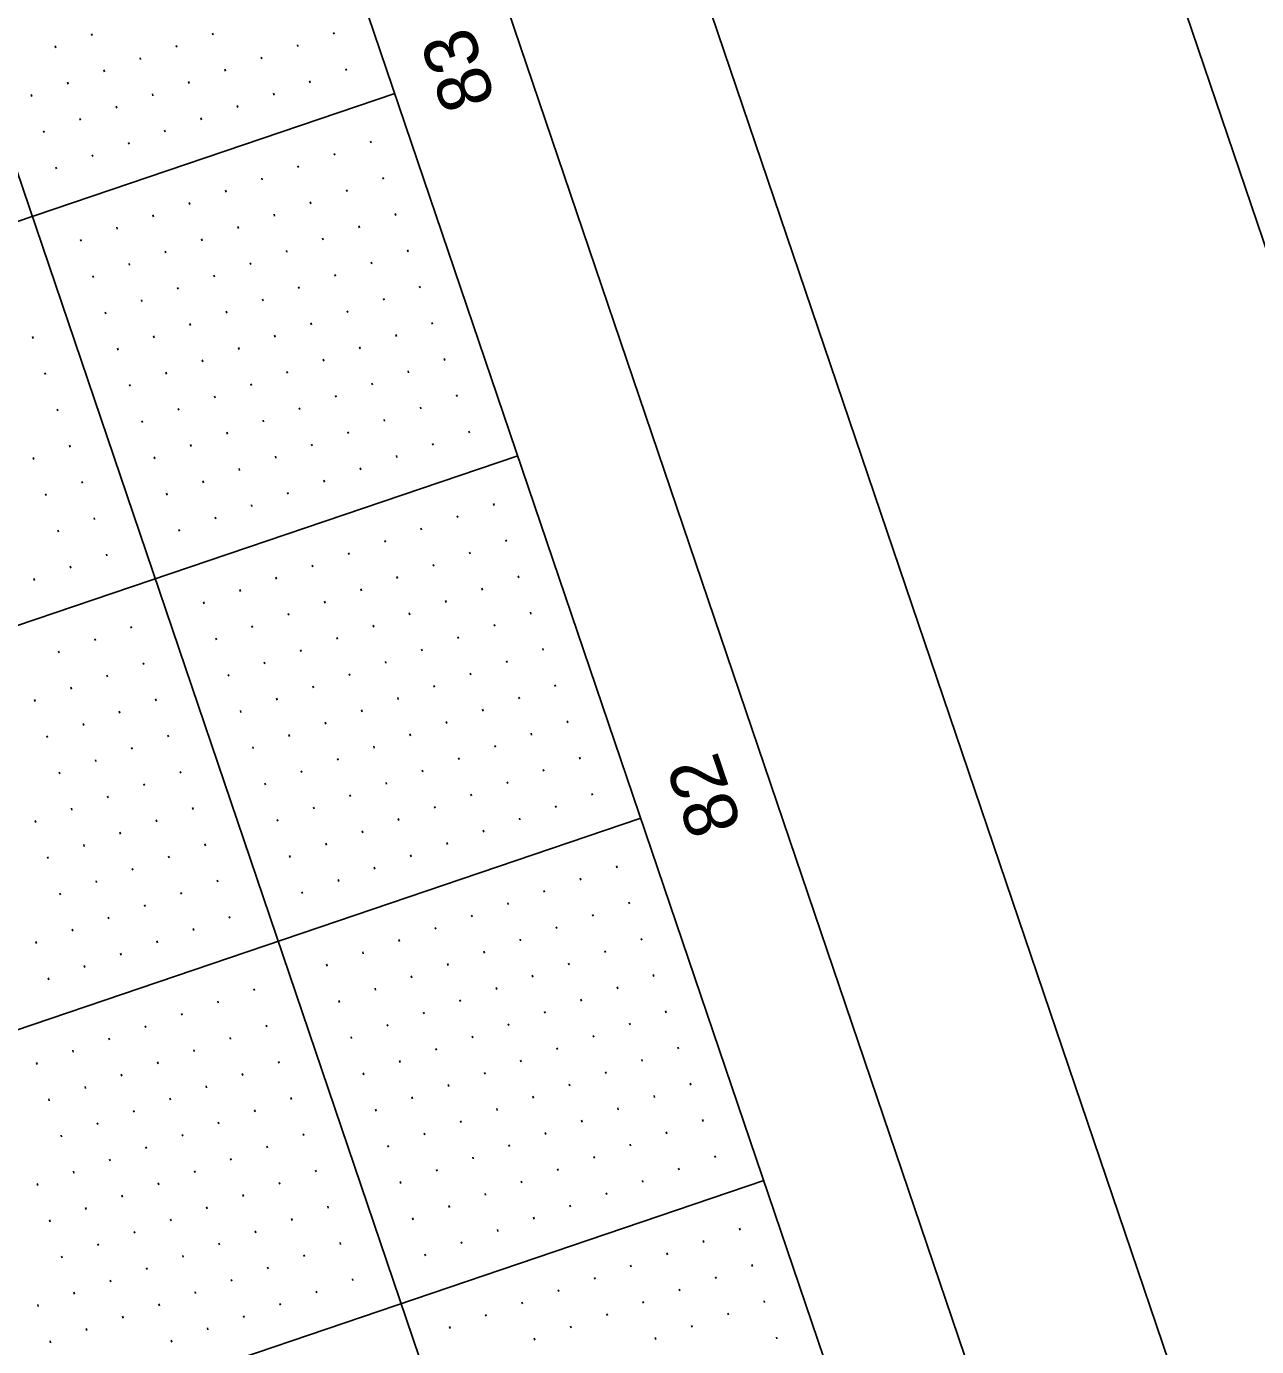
# Model space of a CAD drawing. Extents: x 2150800 to 2152547, y 141860 to 143950.
# Drawn here: x 2151980.1 to 2152140.8, y 143201.8 to 143374.3 of the extents above; entities that cross this region are included whole.
import ezdxf

# ---------------------------------------------------------------- set-up
doc = ezdxf.new("R2010")
doc.units = 0
for name, color, linetype in [('SHT_Plan_Profile_Sheet_Sta_Txt', 7, 'Continuous'), ('SHT_Plot_Shape_Full', 7, 'Continuous'), ('SHT_Plot_Shape_Half', 7, 'Continuous'), ('SHT_Profile_Grid_Major', 7, 'Continuous'), ('SHT_Profile_Grid_Minor', 7, 'Continuous'), ('SHT_Sheet_Border', 7, 'Continuous')]:
    doc.layers.add(name, color=color, linetype=linetype)

msp = doc.modelspace()

# ---------------------------------------------------------------- linework, layer by layer
at = {"layer": 'SHT_Plot_Shape_Full'}
msp.add_lwpolyline([(2151378.63, 141860.13), (2150800.36, 143564.71), (2151936.74, 143950.23), (2152515.02, 142245.65)], close=True, dxfattribs=at)
at = {"layer": 'SHT_Plot_Shape_Half'}
msp.add_lwpolyline([(2151391.39, 141950.92), (2150845.24, 143560.8), (2151886.93, 143914.19), (2152433.08, 142304.31)], close=True, dxfattribs=at)
at = {"layer": 'SHT_Profile_Grid_Major'}
for p, q in [((2152314.16, 142366.92), (2151808.17, 143858.43)), ((2152028.2, 143365.49), (2151554.7, 143204.86)), ((2152044.26, 143318.14), (2151570.77, 143157.51)), ((2152060.32, 143270.79), (2151586.83, 143110.16)), ((2152076.39, 143223.44), (2151602.89, 143062.81))]:
    msp.add_line(p, q, dxfattribs=at)
at = {"layer": 'SHT_Profile_Grid_Minor'}
for p, q in [((2151988.67, 143373.06), (2151988.59, 143373.3)), ((2152004.48, 143373.15), (2152004.4, 143373.39)), ((2152020.29, 143373.23), (2152020.21, 143373.47)), ((2151983.93, 143371.46), (2151983.85, 143371.7)), ((2151999.74, 143371.54), (2151999.66, 143371.78)), ((2152015.56, 143371.63), (2152015.48, 143371.86)), ((2151995.01, 143369.94), (2151994.93, 143370.17)), ((2152010.82, 143370.02), (2152010.74, 143370.26)), ((2151990.27, 143368.33), (2151990.19, 143368.57)), ((2152006.09, 143368.41), (2152006.01, 143368.65)), ((2152021.9, 143368.5), (2152021.82, 143368.73)), ((2151985.54, 143366.72), (2151985.46, 143366.96)), ((2152001.35, 143366.81), (2152001.27, 143367.04)), ((2152017.16, 143366.89), (2152017.08, 143367.13)), ((2151980.8, 143365.12), (2151980.72, 143365.35)), ((2151996.62, 143365.2), (2151996.54, 143365.44)), ((2152007.69, 143363.68), (2152007.61, 143363.92)), ((2152012.43, 143365.29), (2152012.35, 143365.52)), ((2151987.15, 143361.99), (2151987.07, 143362.23)), ((2151991.88, 143363.59), (2151991.8, 143363.83)), ((2152002.96, 143362.07), (2152002.88, 143362.31)), ((2151982.41, 143360.38), (2151982.33, 143360.62)), ((2151998.22, 143360.47), (2151998.14, 143360.7)), ((2151993.49, 143358.86), (2151993.41, 143359.1)), ((2152025.11, 143359.03), (2152025.03, 143359.26)), ((2151988.75, 143357.25), (2151988.67, 143357.49)), ((2152020.37, 143357.42), (2152020.29, 143357.66)), ((2151984.02, 143355.65), (2151983.94, 143355.88)), ((2152015.64, 143355.82), (2152015.56, 143356.05)), ((2152010.9, 143354.21), (2152010.82, 143354.45)), ((2152026.72, 143354.29), (2152026.64, 143354.53)), ((2152006.17, 143352.6), (2152006.09, 143352.84)), ((2152021.98, 143352.69), (2152021.9, 143352.92)), ((2152001.43, 143351), (2152001.35, 143351.23)), ((2152017.25, 143351.08), (2152017.17, 143351.32)), ((2151996.7, 143349.39), (2151996.62, 143349.63)), ((2152012.51, 143349.47), (2152012.43, 143349.71)), ((2152028.32, 143349.56), (2152028.24, 143349.79)), ((2151991.96, 143347.78), (2151991.88, 143348.02)), ((2152007.78, 143347.87), (2152007.7, 143348.1)), ((2152023.59, 143347.95), (2152023.51, 143348.19)), ((2151987.23, 143346.18), (2151987.15, 143346.41)), ((2152003.04, 143346.26), (2152002.96, 143346.5)), ((2152014.12, 143344.74), (2152014.04, 143344.98)), ((2152018.85, 143346.35), (2152018.77, 143346.58)), ((2152029.93, 143344.82), (2152029.85, 143345.06)), ((2151993.57, 143343.05), (2151993.49, 143343.29)), ((2151998.31, 143344.66), (2151998.23, 143344.89)), ((2152009.38, 143343.13), (2152009.3, 143343.37)), ((2152025.19, 143343.22), (2152025.11, 143343.45)), ((2151988.84, 143341.44), (2151988.76, 143341.68)), ((2152004.65, 143341.53), (2152004.57, 143341.76)), ((2152020.46, 143341.61), (2152020.38, 143341.85)), ((2151999.91, 143339.92), (2151999.83, 143340.16)), ((2152015.72, 143340), (2152015.64, 143340.24)), ((2152031.53, 143340.09), (2152031.45, 143340.32)), ((2151995.18, 143338.31), (2151995.1, 143338.55)), ((2152010.99, 143338.4), (2152010.91, 143338.63)), ((2152026.8, 143338.48), (2152026.72, 143338.72)), ((2151990.44, 143336.71), (2151990.36, 143336.94)), ((2152006.25, 143336.79), (2152006.17, 143337.03)), ((2152022.06, 143336.88), (2152021.98, 143337.11)), ((2152001.52, 143335.19), (2152001.44, 143335.42)), ((2152017.33, 143335.27), (2152017.25, 143335.51)), ((2152033.14, 143335.35), (2152033.06, 143335.59)), ((2151980.97, 143333.49), (2151980.89, 143333.73)), ((2151996.78, 143333.58), (2151996.7, 143333.82)), ((2152012.59, 143333.66), (2152012.51, 143333.9)), ((2152028.41, 143333.75), (2152028.33, 143333.98)), ((2151992.05, 143331.97), (2151991.97, 143332.21)), ((2152007.86, 143332.06), (2152007.78, 143332.29)), ((2152023.67, 143332.14), (2152023.59, 143332.38)), ((2152003.13, 143330.45), (2152003.04, 143330.69)), ((2152018.94, 143330.53), (2152018.86, 143330.77)), ((2152034.75, 143330.62), (2152034.67, 143330.85)), ((2151982.58, 143328.76), (2151982.5, 143329)), ((2151998.39, 143328.84), (2151998.31, 143329.08)), ((2152014.2, 143328.93), (2152014.12, 143329.16)), ((2152030.01, 143329.01), (2152029.93, 143329.25)), ((2151993.66, 143327.24), (2151993.57, 143327.47)), ((2152004.73, 143325.72), (2152004.65, 143325.95)), ((2152009.47, 143327.32), (2152009.39, 143327.56)), ((2152020.54, 143325.8), (2152020.46, 143326.04)), ((2152025.28, 143327.41), (2152025.2, 143327.64)), ((2152036.35, 143325.88), (2152036.27, 143326.12)), ((2151984.19, 143324.02), (2151984.1, 143324.26)), ((2152000, 143324.11), (2151999.92, 143324.35)), ((2152015.81, 143324.19), (2152015.73, 143324.43)), ((2152031.62, 143324.28), (2152031.54, 143324.51)), ((2151995.26, 143322.5), (2151995.18, 143322.74)), ((2152011.07, 143322.59), (2152010.99, 143322.82)), ((2152026.88, 143322.67), (2152026.8, 143322.91)), ((2152006.34, 143320.98), (2152006.26, 143321.22)), ((2152022.15, 143321.06), (2152022.07, 143321.3)), ((2152037.96, 143321.15), (2152037.88, 143321.39)), ((2151985.79, 143319.29), (2151985.71, 143319.53)), ((2152001.6, 143319.37), (2152001.52, 143319.61)), ((2152017.41, 143319.46), (2152017.33, 143319.69)), ((2152033.22, 143319.54), (2152033.14, 143319.78)), ((2151981.06, 143317.68), (2151980.98, 143317.92)), ((2151996.87, 143317.77), (2151996.79, 143318)), ((2152012.68, 143317.85), (2152012.6, 143318.09)), ((2152028.49, 143317.94), (2152028.41, 143318.17)), ((2152007.94, 143316.25), (2152007.86, 143316.48)), ((2152023.76, 143316.33), (2152023.67, 143316.57)), ((2151987.4, 143314.56), (2151987.32, 143314.79)), ((2152003.21, 143314.64), (2152003.13, 143314.88)), ((2152019.02, 143314.72), (2152018.94, 143314.96)), ((2151982.66, 143312.95), (2151982.58, 143313.19)), ((2151998.47, 143313.03), (2151998.39, 143313.27)), ((2152014.29, 143313.12), (2152014.2, 143313.35)), ((2152009.55, 143311.51), (2152009.47, 143311.75)), ((2152041.17, 143311.68), (2152041.09, 143311.92)), ((2151989, 143309.82), (2151988.92, 143310.06)), ((2152004.82, 143309.9), (2152004.74, 143310.14)), ((2152031.7, 143308.47), (2152031.62, 143308.7)), ((2152036.44, 143310.07), (2152036.36, 143310.31)), ((2151984.27, 143308.21), (2151984.19, 143308.45)), ((2152000.08, 143308.3), (2152000, 143308.53)), ((2152026.97, 143306.86), (2152026.89, 143307.1)), ((2152042.78, 143306.94), (2152042.7, 143307.18)), ((2151990.61, 143305.09), (2151990.53, 143305.32)), ((2152022.23, 143305.25), (2152022.15, 143305.49)), ((2152038.04, 143305.34), (2152037.96, 143305.57)), ((2151985.88, 143303.48), (2151985.8, 143303.72)), ((2152017.5, 143303.65), (2152017.42, 143303.88)), ((2152033.31, 143303.73), (2152033.23, 143303.97)), ((2151981.14, 143301.87), (2151981.06, 143302.11)), ((2152012.76, 143302.04), (2152012.68, 143302.28)), ((2152028.57, 143302.12), (2152028.49, 143302.36)), ((2152044.39, 143302.21), (2152044.3, 143302.45)), ((2152008.03, 143300.43), (2152007.95, 143300.67)), ((2152023.84, 143300.52), (2152023.76, 143300.75)), ((2152039.65, 143300.6), (2152039.57, 143300.84)), ((2152003.29, 143298.83), (2152003.21, 143299.06)), ((2152019.1, 143298.91), (2152019.02, 143299.15)), ((2152034.92, 143299), (2152034.84, 143299.23)), ((2152014.37, 143297.31), (2152014.29, 143297.54)), ((2152030.18, 143297.39), (2152030.1, 143297.63)), ((2152045.99, 143297.47), (2152045.91, 143297.71)), ((2151993.82, 143295.62), (2151993.74, 143295.85)), ((2152009.63, 143295.7), (2152009.55, 143295.94)), ((2152025.45, 143295.78), (2152025.37, 143296.02)), ((2152041.26, 143295.87), (2152041.18, 143296.1)), ((2151989.09, 143294.01), (2151989.01, 143294.25)), ((2152004.9, 143294.09), (2152004.82, 143294.33)), ((2152020.71, 143294.18), (2152020.63, 143294.41)), ((2152036.52, 143294.26), (2152036.44, 143294.5)), ((2151984.35, 143292.4), (2151984.27, 143292.64)), ((2152015.98, 143292.57), (2152015.9, 143292.81)), ((2152031.79, 143292.65), (2152031.71, 143292.89)), ((2152047.6, 143292.74), (2152047.52, 143292.98)), ((2151995.43, 143290.88), (2151995.35, 143291.12)), ((2152011.24, 143290.96), (2152011.16, 143291.2)), ((2152027.05, 143291.05), (2152026.97, 143291.29)), ((2152038.13, 143289.53), (2152038.05, 143289.76)), ((2152042.86, 143291.13), (2152042.78, 143291.37)), ((2151990.69, 143289.27), (2151990.61, 143289.51)), ((2152006.51, 143289.36), (2152006.43, 143289.59)), ((2152017.58, 143287.84), (2152017.5, 143288.07)), ((2152022.32, 143289.44), (2152022.24, 143289.68)), ((2152033.39, 143287.92), (2152033.31, 143288.16)), ((2152049.2, 143288), (2152049.12, 143288.24)), ((2151981.22, 143286.06), (2151981.14, 143286.3)), ((2151985.96, 143287.67), (2151985.88, 143287.9)), ((2151997.04, 143286.15), (2151996.96, 143286.38)), ((2152012.85, 143286.23), (2152012.77, 143286.47)), ((2152028.66, 143286.31), (2152028.58, 143286.55)), ((2152044.47, 143286.4), (2152044.39, 143286.63)), ((2151992.3, 143284.54), (2151992.22, 143284.78)), ((2152008.11, 143284.62), (2152008.03, 143284.86)), ((2152023.92, 143284.71), (2152023.84, 143284.94)), ((2152039.73, 143284.79), (2152039.65, 143285.03)), ((2151987.57, 143282.93), (2151987.49, 143283.17)), ((2152019.19, 143283.1), (2152019.11, 143283.34)), ((2152035, 143283.18), (2152034.92, 143283.42)), ((2152050.81, 143283.27), (2152050.73, 143283.51)), ((2151982.83, 143281.33), (2151982.75, 143281.56)), ((2151998.64, 143281.41), (2151998.56, 143281.65)), ((2152014.45, 143281.49), (2152014.37, 143281.73)), ((2152030.26, 143281.58), (2152030.18, 143281.82)), ((2152046.08, 143281.66), (2152046, 143281.9)), ((2151993.91, 143279.8), (2151993.83, 143280.04)), ((2152009.72, 143279.89), (2152009.64, 143280.12)), ((2152025.53, 143279.97), (2152025.45, 143280.21)), ((2152041.34, 143280.06), (2152041.26, 143280.29)), ((2151989.17, 143278.2), (2151989.09, 143278.43)), ((2152020.79, 143278.37), (2152020.71, 143278.6)), ((2152036.61, 143278.45), (2152036.53, 143278.69)), ((2152052.42, 143278.53), (2152052.34, 143278.77)), ((2151984.44, 143276.59), (2151984.36, 143276.83)), ((2152000.25, 143276.68), (2152000.17, 143276.91)), ((2152016.06, 143276.76), (2152015.98, 143277)), ((2152031.87, 143276.84), (2152031.79, 143277.08)), ((2152047.68, 143276.93), (2152047.6, 143277.16)), ((2151995.51, 143275.07), (2151995.43, 143275.31)), ((2152011.32, 143275.15), (2152011.24, 143275.39)), ((2152027.14, 143275.24), (2152027.06, 143275.47)), ((2152042.95, 143275.32), (2152042.87, 143275.56)), ((2151990.78, 143273.46), (2151990.7, 143273.7)), ((2152022.4, 143273.63), (2152022.32, 143273.87)), ((2152038.21, 143273.71), (2152038.13, 143273.95)), ((2152054.02, 143273.8), (2152053.94, 143274.04)), ((2151986.04, 143271.86), (2151985.96, 143272.09)), ((2152001.85, 143271.94), (2152001.77, 143272.18)), ((2152017.67, 143272.02), (2152017.59, 143272.26)), ((2152028.74, 143270.5), (2152028.66, 143270.74)), ((2152033.48, 143272.11), (2152033.4, 143272.35)), ((2152044.55, 143270.59), (2152044.47, 143270.82)), ((2152049.29, 143272.19), (2152049.21, 143272.43)), ((2151981.31, 143270.25), (2151981.23, 143270.49)), ((2151997.12, 143270.33), (2151997.04, 143270.57)), ((2152012.93, 143270.42), (2152012.85, 143270.65)), ((2152024.01, 143268.9), (2152023.93, 143269.13)), ((2152039.82, 143268.98), (2152039.74, 143269.22)), ((2151987.65, 143267.12), (2151987.57, 143267.36)), ((2151992.38, 143268.73), (2151992.3, 143268.96)), ((2152003.46, 143267.21), (2152003.38, 143267.44)), ((2152019.27, 143267.29), (2152019.19, 143267.53)), ((2152035.08, 143267.37), (2152035, 143267.61)), ((2151982.91, 143265.52), (2151982.83, 143265.75)), ((2151998.73, 143265.6), (2151998.65, 143265.84)), ((2152014.54, 143265.68), (2152014.46, 143265.92)), ((2152030.35, 143265.77), (2152030.27, 143266)), ((2151993.99, 143263.99), (2151993.91, 143264.23)), ((2152025.61, 143264.16), (2152025.53, 143264.4)), ((2152057.24, 143264.33), (2152057.16, 143264.57)), ((2151989.26, 143262.39), (2151989.18, 143262.62)), ((2152005.07, 143262.47), (2152004.99, 143262.71)), ((2152020.88, 143262.55), (2152020.8, 143262.79)), ((2152052.5, 143262.72), (2152052.42, 143262.96)), ((2151984.52, 143260.78), (2151984.44, 143261.02)), ((2152000.33, 143260.86), (2152000.25, 143261.1)), ((2152016.14, 143260.95), (2152016.06, 143261.19)), ((2152047.77, 143261.12), (2152047.69, 143261.35)), ((2151995.6, 143259.26), (2151995.52, 143259.49)), ((2152043.03, 143259.51), (2152042.95, 143259.75)), ((2152058.84, 143259.59), (2152058.76, 143259.83)), ((2151990.86, 143257.65), (2151990.78, 143257.89)), ((2152006.67, 143257.74), (2152006.59, 143257.97)), ((2152038.3, 143257.9), (2152038.22, 143258.14)), ((2152054.11, 143257.99), (2152054.03, 143258.22)), ((2151986.13, 143256.05), (2151986.05, 143256.28)), ((2152001.94, 143256.13), (2152001.86, 143256.37)), ((2152033.56, 143256.3), (2152033.48, 143256.53)), ((2152049.37, 143256.38), (2152049.29, 143256.62)), ((2151981.39, 143254.44), (2151981.31, 143254.68)), ((2151997.2, 143254.52), (2151997.12, 143254.76)), ((2152028.83, 143254.69), (2152028.75, 143254.93)), ((2152044.64, 143254.77), (2152044.56, 143255.01)), ((2152055.71, 143253.25), (2152055.63, 143253.49)), ((2152060.45, 143254.86), (2152060.37, 143255.1)), ((2151992.47, 143252.92), (2151992.39, 143253.15)), ((2152024.09, 143253.08), (2152024.01, 143253.32)), ((2152035.17, 143251.56), (2152035.09, 143251.8)), ((2152039.9, 143253.17), (2152039.82, 143253.41)), ((2152050.98, 143251.65), (2152050.9, 143251.88)), ((2151987.73, 143251.31), (2151987.65, 143251.55)), ((2152019.36, 143251.48), (2152019.28, 143251.72)), ((2152030.43, 143249.96), (2152030.35, 143250.19)), ((2152046.24, 143250.04), (2152046.16, 143250.28)), ((2152062.05, 143250.12), (2152061.97, 143250.36)), ((2151983, 143249.7), (2151982.92, 143249.94)), ((2152009.89, 143248.27), (2152009.81, 143248.5)), ((2152025.7, 143248.35), (2152025.62, 143248.59)), ((2152041.51, 143248.43), (2152041.43, 143248.67)), ((2152057.32, 143248.52), (2152057.24, 143248.75)), ((2152005.15, 143246.66), (2152005.07, 143246.9)), ((2152020.96, 143246.74), (2152020.88, 143246.98)), ((2152036.77, 143246.83), (2152036.69, 143247.06)), ((2152052.58, 143246.91), (2152052.5, 143247.15)), ((2152000.42, 143245.05), (2152000.34, 143245.29)), ((2152032.04, 143245.22), (2152031.96, 143245.46)), ((2152047.85, 143245.31), (2152047.77, 143245.54)), ((2152063.66, 143245.39), (2152063.58, 143245.63)), ((2151995.68, 143243.45), (2151995.6, 143243.68)), ((2152011.49, 143243.53), (2152011.41, 143243.77)), ((2152027.3, 143243.61), (2152027.22, 143243.85)), ((2152043.11, 143243.7), (2152043.03, 143243.94)), ((2152058.93, 143243.78), (2152058.85, 143244.02)), ((2151990.95, 143241.84), (2151990.87, 143242.08)), ((2152006.76, 143241.92), (2152006.68, 143242.16)), ((2152022.57, 143242.01), (2152022.49, 143242.25)), ((2152038.38, 143242.09), (2152038.3, 143242.33)), ((2152054.19, 143242.18), (2152054.11, 143242.41)), ((2151986.21, 143240.23), (2151986.13, 143240.47)), ((2152002.02, 143240.32), (2152001.94, 143240.55)), ((2152033.65, 143240.49), (2152033.56, 143240.72)), ((2152049.46, 143240.57), (2152049.38, 143240.81)), ((2152065.27, 143240.65), (2152065.19, 143240.89)), ((2151981.48, 143238.63), (2151981.4, 143238.86)), ((2151997.29, 143238.71), (2151997.21, 143238.95)), ((2152013.1, 143238.8), (2152013.02, 143239.03)), ((2152028.91, 143238.88), (2152028.83, 143239.12)), ((2152044.72, 143238.96), (2152044.64, 143239.2)), ((2152060.53, 143239.05), (2152060.45, 143239.28)), ((2151992.55, 143237.11), (2151992.47, 143237.34)), ((2152008.36, 143237.19), (2152008.28, 143237.43)), ((2152024.18, 143237.27), (2152024.09, 143237.51)), ((2152039.99, 143237.36), (2152039.91, 143237.59)), ((2152055.8, 143237.44), (2152055.72, 143237.68)), ((2151987.82, 143235.5), (2151987.74, 143235.74)), ((2152003.63, 143235.58), (2152003.55, 143235.82)), ((2152035.25, 143235.75), (2152035.17, 143235.99)), ((2152051.06, 143235.84), (2152050.98, 143236.07)), ((2152062.14, 143234.31), (2152062.06, 143234.55)), ((2152066.87, 143235.92), (2152066.79, 143236.16)), ((2151983.08, 143233.89), (2151983, 143234.13)), ((2151998.89, 143233.98), (2151998.81, 143234.21)), ((2152014.71, 143234.06), (2152014.62, 143234.3)), ((2152025.78, 143232.54), (2152025.7, 143232.78)), ((2152030.52, 143234.14), (2152030.44, 143234.38)), ((2152041.59, 143232.62), (2152041.51, 143232.86)), ((2152046.33, 143234.23), (2152046.25, 143234.47)), ((2152057.4, 143232.71), (2152057.32, 143232.94)), ((2151994.16, 143232.37), (2151994.08, 143232.61)), ((2152005.24, 143230.85), (2152005.15, 143231.08)), ((2152009.97, 143232.45), (2152009.89, 143232.69)), ((2152036.86, 143231.02), (2152036.78, 143231.25)), ((2152052.67, 143231.1), (2152052.59, 143231.34)), ((2152068.48, 143231.18), (2152068.4, 143231.42)), ((2151984.69, 143229.16), (2151984.61, 143229.39)), ((2151989.42, 143230.76), (2151989.34, 143231)), ((2152000.5, 143229.24), (2152000.42, 143229.48)), ((2152016.31, 143229.33), (2152016.23, 143229.56)), ((2152032.12, 143229.41), (2152032.04, 143229.65)), ((2152047.93, 143229.49), (2152047.85, 143229.73)), ((2152063.74, 143229.58), (2152063.66, 143229.81)), ((2151995.77, 143227.64), (2151995.69, 143227.87)), ((2152011.58, 143227.72), (2152011.5, 143227.96)), ((2152027.39, 143227.8), (2152027.31, 143228.04)), ((2152043.2, 143227.89), (2152043.12, 143228.12)), ((2152059.01, 143227.97), (2152058.93, 143228.21)), ((2151991.03, 143226.03), (2151990.95, 143226.27)), ((2152006.84, 143226.11), (2152006.76, 143226.35)), ((2152038.46, 143226.28), (2152038.38, 143226.52)), ((2152054.28, 143226.37), (2152054.19, 143226.6)), ((2152070.09, 143226.45), (2152070.01, 143226.69)), ((2151986.3, 143224.42), (2151986.22, 143224.66)), ((2152002.11, 143224.51), (2152002.03, 143224.74)), ((2152017.92, 143224.59), (2152017.84, 143224.83)), ((2152033.73, 143224.68), (2152033.65, 143224.91)), ((2152049.54, 143224.76), (2152049.46, 143225)), ((2152065.35, 143224.84), (2152065.27, 143225.08)), ((2151981.56, 143222.82), (2151981.48, 143223.05)), ((2151997.37, 143222.9), (2151997.29, 143223.14)), ((2152013.18, 143222.98), (2152013.1, 143223.22)), ((2152028.99, 143223.07), (2152028.91, 143223.31)), ((2152044.81, 143223.15), (2152044.72, 143223.39)), ((2152060.62, 143223.24), (2152060.54, 143223.47)), ((2151992.64, 143221.29), (2151992.56, 143221.53)), ((2152008.45, 143221.38), (2152008.37, 143221.62)), ((2152040.07, 143221.55), (2152039.99, 143221.78)), ((2152055.88, 143221.63), (2152055.8, 143221.87)), ((2151987.9, 143219.69), (2151987.82, 143219.92)), ((2152003.71, 143219.77), (2152003.63, 143220.01)), ((2152019.52, 143219.86), (2152019.44, 143220.09)), ((2152035.34, 143219.94), (2152035.26, 143220.18)), ((2152051.15, 143220.02), (2152051.07, 143220.26)), ((2151983.17, 143218.08), (2151983.09, 143218.32)), ((2151998.98, 143218.17), (2151998.9, 143218.4)), ((2152014.79, 143218.25), (2152014.71, 143218.49)), ((2152030.6, 143218.33), (2152030.52, 143218.57)), ((2152046.41, 143218.42), (2152046.33, 143218.65)), ((2151994.24, 143216.56), (2151994.16, 143216.8)), ((2152010.05, 143216.64), (2152009.97, 143216.88)), ((2152041.68, 143216.81), (2152041.6, 143217.05)), ((2152068.56, 143215.37), (2152068.48, 143215.61)), ((2152073.3, 143216.98), (2152073.22, 143217.22)), ((2151989.51, 143214.95), (2151989.43, 143215.19)), ((2152005.32, 143215.04), (2152005.24, 143215.27)), ((2152021.13, 143215.12), (2152021.05, 143215.36)), ((2152032.21, 143213.6), (2152032.13, 143213.84)), ((2152036.94, 143215.21), (2152036.86, 143215.44)), ((2152063.83, 143213.77), (2152063.75, 143214)), ((2151984.77, 143213.35), (2151984.69, 143213.58)), ((2152000.58, 143213.43), (2152000.5, 143213.67)), ((2152011.66, 143211.91), (2152011.58, 143212.15)), ((2152016.4, 143213.51), (2152016.32, 143213.75)), ((2152059.09, 143212.16), (2152059.01, 143212.4)), ((2152074.91, 143212.24), (2152074.82, 143212.48)), ((2151991.11, 143210.22), (2151991.03, 143210.45)), ((2151995.85, 143211.82), (2151995.77, 143212.06)), ((2152006.93, 143210.3), (2152006.85, 143210.54)), ((2152022.74, 143210.39), (2152022.66, 143210.62)), ((2152054.36, 143210.55), (2152054.28, 143210.79)), ((2152070.17, 143210.64), (2152070.09, 143210.87)), ((2151986.38, 143208.61), (2151986.3, 143208.85)), ((2152002.19, 143208.7), (2152002.11, 143208.93)), ((2152018, 143208.78), (2152017.92, 143209.02)), ((2152049.62, 143208.95), (2152049.54, 143209.18)), ((2152065.44, 143209.03), (2152065.36, 143209.27)), ((2151981.64, 143207.01), (2151981.56, 143207.24)), ((2151997.46, 143207.09), (2151997.38, 143207.33)), ((2152013.27, 143207.17), (2152013.19, 143207.41)), ((2152044.89, 143207.34), (2152044.81, 143207.58)), ((2152060.7, 143207.43), (2152060.62, 143207.66)), ((2152076.51, 143207.51), (2152076.43, 143207.75)), ((2151992.72, 143205.48), (2151992.64, 143205.72)), ((2152008.53, 143205.57), (2152008.45, 143205.8)), ((2152040.15, 143205.74), (2152040.07, 143205.97)), ((2152055.97, 143205.82), (2152055.89, 143206.06)), ((2152071.78, 143205.9), (2152071.7, 143206.14)), ((2151987.99, 143203.88), (2151987.91, 143204.11)), ((2152003.8, 143203.96), (2152003.72, 143204.2)), ((2152035.42, 143204.13), (2152035.34, 143204.37)), ((2152051.23, 143204.21), (2152051.15, 143204.45)), ((2152067.04, 143204.3), (2152066.96, 143204.53)), ((2151983.25, 143202.27), (2151983.17, 143202.51)), ((2151999.06, 143202.35), (2151998.98, 143202.59)), ((2152046.5, 143202.61), (2152046.42, 143202.84)), ((2152062.31, 143202.69), (2152062.23, 143202.93)), ((2152078.12, 143202.77), (2152078.04, 143203.01))]:
    msp.add_line(p, q, dxfattribs=at)
at = {"layer": 'SHT_Sheet_Border'}
msp.add_line((2152361.51, 142382.99), (2151939.85, 143625.91), dxfattribs=at)
msp.add_lwpolyline([(2151383.74, 142051.28), (2150877.75, 143542.79), (2151872.09, 143880.12), (2152378.08, 142388.61)], close=True, dxfattribs=at)

# ---------------------------------------------------------------- texts
at = {"layer": 'SHT_Plan_Profile_Sheet_Sta_Txt'}
for s, p in [('83', (2152041.41, 143364.68)), ('82', (2152073.58, 143269.86))]:
    msp.add_text(s, height=7, rotation=108.7393, dxfattribs=at).set_placement(p)

doc.saveas('drawing.dxf')
